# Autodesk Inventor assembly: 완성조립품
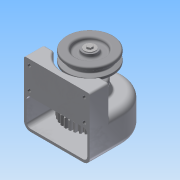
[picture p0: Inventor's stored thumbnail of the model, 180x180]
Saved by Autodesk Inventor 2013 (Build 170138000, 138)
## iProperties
Created: 2015-02
Part Number: 완성조립품
Document SubType Name: Assembly
Designer: Administrator
Author: Administrator
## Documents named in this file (14)
- C:\Documents and Settings\Administrator\바탕 화면\450214V1002\완성조립품.iam
- C:\Documents and Settings\Administrator\바탕 화면\450214V1002\1-본체.ipt
- C:\Documents and Settings\Administrator\바탕 화면\450214V1002\베어링 6001.ipt
- C:\Documents and Settings\Administrator\바탕 화면\450214V1002\축.ipt
- C:\Documents and Settings\Administrator\바탕 화면\450214V1002\키5x5.ipt
- C:\Documents and Settings\Administrator\바탕 화면\450214V1002\스퍼기어.ipt
- C:\Documents and Settings\Administrator\바탕 화면\450214V1002\축커버.ipt
- C:\Documents and Settings\Administrator\바탕 화면\450214V1002\M3x0.5.ipt
- C:\Documents and Settings\Administrator\바탕 화면\450214V1002\오일실.ipt
- C:\Documents and Settings\Administrator\바탕 화면\450214V1002\4-벨트풀리.ipt
- C:\Documents and Settings\Administrator\바탕 화면\450214V1002\키4x4.ipt
- C:\Documents and Settings\Administrator\바탕 화면\450214V1002\와샤.ipt
- C:\Documents and Settings\Administrator\바탕 화면\450214V1002\M5x0.8.ipt
- M5x0.8.ipt
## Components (7 placed, 4 different names)
1. 1-본체:1
2. 4-벨트풀리:1 — 각도:4
3. M5x0.8:1 — 각도:5
4. M3x0.5:1
5. M3x0.5:2
6. M3x0.5:3
7. M3x0.5:4
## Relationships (2: Angle 2)
- 각도:4 [Angle]: 4-벨트풀리:1
- 각도:5 [Angle]: M5x0.8:1
